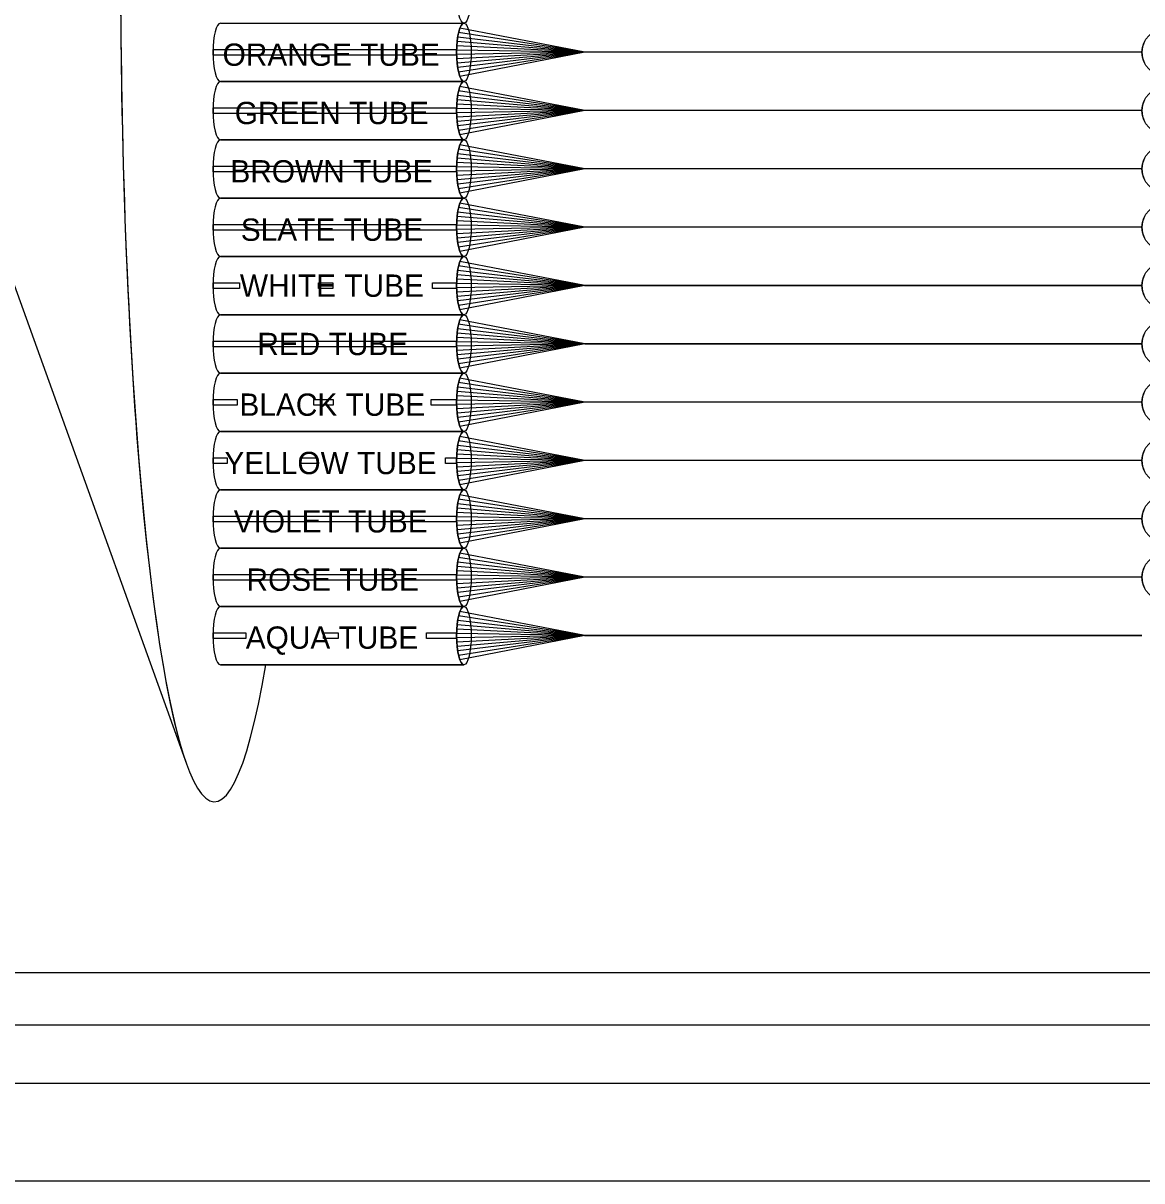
# Model space of a CAD drawing. Extents: x 1805893 to 1833564, y 708898 to 716199.
# Drawn here: x 1831608.1 to 1831723.1, y 714257.9 to 714377 of the extents above; entities that cross this region are included whole.
import ezdxf

# ---------------------------------------------------------------- set-up
doc = ezdxf.new("R2010")
doc.units = 0
for name, color, linetype in [('BR_P_Sub_Hidden', 7, 'Continuous'), ('SH_Border', 7, 'Continuous'), ('SH_Cut_Line', 7, 'Continuous'), ('SH_Data', 7, 'Continuous')]:
    doc.layers.add(name, color=color, linetype=linetype)

msp = doc.modelspace()

# ---------------------------------------------------------------- linework, layer by layer
at = {"layer": 'BR_P_Sub_Hidden'}
for points in [[(1831500.32, 714509.57), (1831957.51, 714509.57), (1831957.51, 714273.91), (1831500.32, 714273.91)], [(1831570.12, 714505.91), (1831894.14, 714505.91), (1831894.14, 714279.3), (1831570.12, 714279.3)]]:
    msp.add_lwpolyline(points, close=True, dxfattribs=at)
at = {"layer": 'SH_Border'}
msp.add_lwpolyline([(1831362.49, 714687.91), (1831992.49, 714687.91), (1831992.49, 714267.91), (1831362.49, 714267.91)], close=True, dxfattribs=at)
at = {"layer": 'SH_Cut_Line'}
msp.add_lwpolyline([(1831322.49, 714257.91), (1832002.49, 714257.91), (1832002.49, 714697.91), (1831322.49, 714697.91)], close=True, dxfattribs=at)
at = {"layer": 'SH_Data'}
for p, q in [((1831628.36, 714376.99), (1831653.41, 714376.99)), ((1831665.83, 714373.99), (1831652.85, 714376.01)), ((1831665.83, 714373.99), (1831652.98, 714376.46)), ((1831665.83, 714373.99), (1831652.71, 714375.11)), ((1831665.83, 714373.99), (1831652.77, 714375.56)), ((1831665.83, 714373.99), (1831652.66, 714374.21)), ((1831665.83, 714373.99), (1831652.66, 714373.76)), ((1831665.83, 714373.99), (1831652.67, 714374.66)), ((1831665.83, 714373.99), (1831652.67, 714373.31)), ((1831665.83, 714373.99), (1831652.71, 714372.86)), ((1831665.83, 714373.99), (1831652.77, 714372.41)), ((1831665.83, 714373.99), (1831652.85, 714371.96)), ((1831665.83, 714373.99), (1831652.98, 714371.51)), ((1831723.13, 714373.99), (1831665.83, 714373.99)), ((1831723.13, 714373.99), (1831665.83, 714373.99)), ((1831628.36, 714370.99), (1831653.41, 714370.99)), ((1831653.41, 714370.99), (1831628.36, 714370.99)), ((1831665.83, 714367.99), (1831652.98, 714370.46)), ((1831665.83, 714367.99), (1831652.71, 714369.11)), ((1831665.83, 714367.99), (1831652.77, 714369.56)), ((1831665.83, 714367.99), (1831652.85, 714370.01)), ((1831665.83, 714367.99), (1831652.66, 714368.21)), ((1831665.83, 714367.99), (1831652.66, 714367.76)), ((1831665.83, 714367.99), (1831652.67, 714368.66)), ((1831665.83, 714367.99), (1831652.67, 714367.31)), ((1831665.83, 714367.99), (1831652.71, 714366.86)), ((1831665.83, 714367.99), (1831652.77, 714366.41)), ((1831665.83, 714367.99), (1831652.85, 714365.96)), ((1831665.83, 714367.99), (1831652.98, 714365.51)), ((1831723.13, 714367.99), (1831665.83, 714367.99)), ((1831723.13, 714367.99), (1831665.83, 714367.99)), ((1831653.41, 714364.99), (1831628.36, 714364.99)), ((1831628.36, 714364.99), (1831653.41, 714364.99)), ((1831665.83, 714361.99), (1831652.98, 714364.46)), ((1831665.83, 714361.99), (1831652.71, 714363.11)), ((1831665.83, 714361.99), (1831652.77, 714363.56)), ((1831665.83, 714361.99), (1831652.85, 714364.01)), ((1831665.83, 714361.99), (1831652.66, 714362.21)), ((1831665.83, 714361.99), (1831652.66, 714361.76)), ((1831665.83, 714361.99), (1831652.67, 714362.66)), ((1831665.83, 714361.99), (1831652.67, 714361.31)), ((1831665.83, 714361.99), (1831652.71, 714360.86)), ((1831665.83, 714361.99), (1831652.77, 714360.41)), ((1831665.83, 714361.99), (1831652.85, 714359.96)), ((1831665.83, 714361.99), (1831652.98, 714359.51)), ((1831723.13, 714361.99), (1831665.83, 714361.99)), ((1831723.13, 714361.99), (1831665.83, 714361.99)), ((1831653.41, 714358.99), (1831628.36, 714358.99)), ((1831628.36, 714358.99), (1831653.41, 714358.99)), ((1831665.83, 714355.99), (1831652.98, 714358.46)), ((1831665.83, 714355.99), (1831652.71, 714357.11)), ((1831665.83, 714355.99), (1831652.77, 714357.56)), ((1831665.83, 714355.99), (1831652.85, 714358.01)), ((1831665.83, 714355.99), (1831652.66, 714356.21)), ((1831665.83, 714355.99), (1831652.66, 714355.76)), ((1831665.83, 714355.99), (1831652.67, 714356.66)), ((1831665.83, 714355.99), (1831652.67, 714355.31)), ((1831665.83, 714355.99), (1831652.71, 714354.86)), ((1831665.83, 714355.99), (1831652.77, 714354.41)), ((1831665.83, 714355.99), (1831652.85, 714353.96)), ((1831665.83, 714355.99), (1831652.98, 714353.51)), ((1831723.13, 714355.99), (1831665.83, 714355.99)), ((1831723.13, 714355.99), (1831665.83, 714355.99)), ((1831653.41, 714352.99), (1831628.36, 714352.99)), ((1831628.36, 714352.99), (1831653.41, 714352.99)), ((1831665.83, 714349.99), (1831652.98, 714352.46)), ((1831665.83, 714349.99), (1831652.71, 714351.11)), ((1831665.83, 714349.99), (1831652.77, 714351.56)), ((1831665.83, 714349.99), (1831652.85, 714352.01)), ((1831665.83, 714349.99), (1831652.66, 714350.21)), ((1831665.83, 714349.99), (1831652.66, 714349.76)), ((1831665.83, 714349.99), (1831652.67, 714350.66)), ((1831665.83, 714349.99), (1831652.67, 714349.31)), ((1831665.83, 714349.99), (1831652.71, 714348.86)), ((1831665.83, 714349.99), (1831652.77, 714348.41)), ((1831665.83, 714349.99), (1831652.85, 714347.96)), ((1831665.83, 714349.99), (1831652.98, 714347.51)), ((1831723.13, 714349.99), (1831665.83, 714349.99)), ((1831723.13, 714349.96), (1831665.83, 714349.94)), ((1831653.41, 714346.99), (1831628.36, 714346.99)), ((1831628.36, 714346.99), (1831653.41, 714346.99)), ((1831665.83, 714343.99), (1831652.98, 714346.46)), ((1831665.83, 714343.99), (1831652.71, 714345.11)), ((1831665.83, 714343.99), (1831652.77, 714345.56)), ((1831665.83, 714343.99), (1831652.85, 714346.01)), ((1831665.83, 714343.99), (1831652.66, 714344.21)), ((1831665.83, 714343.99), (1831652.66, 714343.76)), ((1831665.83, 714343.99), (1831652.67, 714344.66)), ((1831665.83, 714343.99), (1831652.67, 714343.31)), ((1831665.83, 714343.99), (1831652.71, 714342.86)), ((1831665.83, 714343.99), (1831652.77, 714342.41)), ((1831665.83, 714343.99), (1831652.85, 714341.96)), ((1831665.83, 714343.99), (1831652.98, 714341.51)), ((1831665.83, 714343.99), (1831723.13, 714343.99)), ((1831723.13, 714343.99), (1831665.83, 714343.99)), ((1831653.41, 714340.99), (1831628.36, 714340.99)), ((1831628.36, 714340.99), (1831653.41, 714340.99)), ((1831665.83, 714337.99), (1831652.98, 714340.46)), ((1831665.83, 714337.99), (1831652.71, 714339.11)), ((1831665.83, 714337.99), (1831652.77, 714339.56)), ((1831665.83, 714337.99), (1831652.85, 714340.01)), ((1831665.83, 714337.99), (1831652.66, 714338.21)), ((1831665.83, 714337.99), (1831652.66, 714337.76)), ((1831665.83, 714337.99), (1831652.67, 714338.66)), ((1831665.83, 714337.99), (1831652.67, 714337.31)), ((1831665.83, 714337.99), (1831652.71, 714336.86)), ((1831665.83, 714337.99), (1831652.77, 714336.41)), ((1831665.83, 714337.99), (1831652.85, 714335.96)), ((1831665.83, 714337.99), (1831652.98, 714335.51)), ((1831723.13, 714337.99), (1831665.83, 714337.99)), ((1831723.13, 714337.99), (1831665.83, 714337.99)), ((1831628.36, 714334.99), (1831653.41, 714334.99)), ((1831653.41, 714334.99), (1831628.36, 714334.99)), ((1831665.83, 714331.99), (1831652.98, 714334.46)), ((1831665.83, 714331.99), (1831652.77, 714333.56)), ((1831665.83, 714331.99), (1831652.85, 714334.01)), ((1831665.83, 714331.99), (1831652.66, 714332.21)), ((1831665.83, 714331.99), (1831652.66, 714331.76)), ((1831665.83, 714331.99), (1831652.67, 714332.66)), ((1831665.83, 714331.99), (1831652.67, 714331.31)), ((1831665.83, 714331.99), (1831652.71, 714333.11)), ((1831665.83, 714331.99), (1831652.71, 714330.86)), ((1831665.83, 714331.99), (1831652.77, 714330.41)), ((1831665.83, 714331.99), (1831652.85, 714329.96)), ((1831665.83, 714331.99), (1831652.98, 714329.51)), ((1831723.13, 714331.99), (1831665.83, 714331.99)), ((1831723.13, 714331.99), (1831665.83, 714331.99)), ((1831653.41, 714328.99), (1831628.36, 714328.99)), ((1831628.36, 714328.99), (1831653.41, 714328.99)), ((1831665.83, 714325.99), (1831652.98, 714328.46)), ((1831665.83, 714325.99), (1831652.77, 714327.56)), ((1831665.83, 714325.99), (1831652.85, 714328.01)), ((1831665.83, 714325.99), (1831652.66, 714326.21)), ((1831665.83, 714325.99), (1831652.67, 714326.66)), ((1831665.83, 714325.99), (1831652.71, 714327.11)), ((1831665.83, 714325.99), (1831652.66, 714325.76)), ((1831665.83, 714325.99), (1831652.67, 714325.31)), ((1831665.83, 714325.99), (1831652.71, 714324.86)), ((1831665.83, 714325.99), (1831652.77, 714324.41)), ((1831665.83, 714325.99), (1831652.85, 714323.96)), ((1831665.83, 714325.99), (1831652.98, 714323.51)), ((1831723.13, 714325.99), (1831665.83, 714325.99)), ((1831723.13, 714325.99), (1831665.83, 714325.99)), ((1831653.41, 714322.99), (1831628.36, 714322.99)), ((1831628.36, 714322.99), (1831653.41, 714322.99)), ((1831665.83, 714319.99), (1831652.98, 714322.46)), ((1831665.83, 714319.99), (1831652.77, 714321.56)), ((1831665.83, 714319.99), (1831652.85, 714322.01)), ((1831665.83, 714319.99), (1831652.66, 714320.21)), ((1831665.83, 714319.99), (1831652.67, 714320.66)), ((1831665.83, 714319.99), (1831652.71, 714321.11)), ((1831665.83, 714319.99), (1831652.66, 714319.76)), ((1831665.83, 714319.99), (1831652.67, 714319.31)), ((1831665.83, 714319.99), (1831652.71, 714318.86)), ((1831665.83, 714319.99), (1831652.77, 714318.41)), ((1831665.83, 714319.99), (1831652.85, 714317.96)), ((1831665.83, 714319.99), (1831652.98, 714317.51)), ((1831723.13, 714319.99), (1831665.83, 714319.99)), ((1831723.13, 714319.99), (1831665.83, 714319.99)), ((1831653.41, 714316.99), (1831628.36, 714316.99)), ((1831628.36, 714316.99), (1831653.41, 714316.99)), ((1831665.83, 714313.99), (1831652.77, 714315.56)), ((1831665.83, 714313.99), (1831652.85, 714316.01)), ((1831665.83, 714313.99), (1831652.98, 714316.46)), ((1831665.83, 714313.99), (1831652.66, 714314.21)), ((1831665.83, 714313.99), (1831652.67, 714314.66)), ((1831665.83, 714313.99), (1831652.71, 714315.11)), ((1831665.83, 714313.99), (1831652.66, 714313.76)), ((1831665.83, 714313.99), (1831652.67, 714313.31)), ((1831665.83, 714313.99), (1831652.71, 714312.86)), ((1831665.83, 714313.99), (1831652.77, 714312.41)), ((1831665.83, 714313.99), (1831652.85, 714311.96)), ((1831665.83, 714313.99), (1831652.98, 714311.51)), ((1831723.13, 714313.99), (1831665.83, 714313.99)), ((1831723.13, 714313.96), (1831665.83, 714313.94)), ((1831653.41, 714310.99), (1831628.36, 714310.99)), ((1831628.36, 714310.99), (1831653.41, 714310.99)), ((1831653.41, 714310.99), (1831633.05, 714310.99))]:
    msp.add_line(p, q, dxfattribs=at)
msp.add_lwpolyline([(1831624.88, 714465.18), (1831595.29, 714382.99), (1831624.88, 714300.79)], dxfattribs=at)
msp.add_lwpolyline([(1831624.88, 714465.18), (1831595.29, 714382.99), (1831624.88, 714300.79)], dxfattribs=at)
for points in [[(1831627.61, 714374.29), (1831652.66, 714374.29), (1831652.66, 714373.69), (1831627.61, 714373.69)], [(1831627.61, 714368.29), (1831652.66, 714368.29), (1831652.66, 714367.69), (1831627.61, 714367.69)], [(1831627.61, 714362.29), (1831652.66, 714362.29), (1831652.66, 714361.69), (1831627.61, 714361.69)], [(1831627.61, 714356.29), (1831652.66, 714356.29), (1831652.66, 714355.69), (1831627.61, 714355.69)], [(1831627.61, 714350.29), (1831630.34, 714350.29), (1831630.34, 714349.69), (1831627.61, 714349.69)], [(1831638.44, 714350.29), (1831639.92, 714350.29), (1831639.92, 714349.69), (1831638.44, 714349.69)], [(1831650.17, 714350.29), (1831652.66, 714350.29), (1831652.66, 714349.69), (1831650.17, 714349.69)], [(1831627.61, 714344.29), (1831652.66, 714344.29), (1831652.66, 714343.69), (1831627.61, 714343.69)], [(1831627.61, 714338.29), (1831630.09, 714338.29), (1831630.09, 714337.69), (1831627.61, 714337.69)], [(1831637.99, 714338.29), (1831639.96, 714338.29), (1831639.96, 714337.69), (1831637.99, 714337.69)], [(1831650.05, 714338.29), (1831652.66, 714338.29), (1831652.66, 714337.69), (1831650.05, 714337.69)], [(1831627.61, 714332.29), (1831629.07, 714332.29), (1831629.07, 714331.69), (1831627.61, 714331.69)], [(1831636.57, 714332.29), (1831638.29, 714332.29), (1831638.29, 714331.69), (1831636.57, 714331.69)], [(1831651.53, 714332.29), (1831652.66, 714332.29), (1831652.66, 714331.69), (1831651.53, 714331.69)], [(1831627.61, 714326.29), (1831652.66, 714326.29), (1831652.66, 714325.69), (1831627.61, 714325.69)], [(1831627.61, 714320.29), (1831652.66, 714320.29), (1831652.66, 714319.69), (1831627.61, 714319.69)], [(1831627.61, 714314.29), (1831630.98, 714314.29), (1831630.98, 714313.69), (1831627.61, 714313.69)], [(1831638.97, 714314.29), (1831640.49, 714314.29), (1831640.49, 714313.69), (1831638.97, 714313.69)], [(1831649.56, 714314.29), (1831652.66, 714314.29), (1831652.66, 714313.69), (1831649.56, 714313.69)]]:
    msp.add_lwpolyline(points, close=True, dxfattribs=at)
for centre in [(1831725.55, 714373.99), (1831725.55, 714367.99), (1831725.55, 714361.99), (1831725.55, 714355.99), (1831725.55, 714349.99), (1831725.55, 714343.99), (1831725.55, 714337.99), (1831725.55, 714331.99), (1831725.55, 714325.99), (1831725.55, 714319.99)]:
    msp.add_circle(centre, 2.41, dxfattribs=at)
for centre in [(1831725.55, 714373.99), (1831725.55, 714367.99), (1831725.55, 714361.99), (1831725.55, 714355.99), (1831725.55, 714349.99), (1831725.55, 714343.99), (1831725.55, 714337.99), (1831725.55, 714331.99), (1831725.55, 714325.99), (1831725.55, 714319.99)]:
    msp.add_arc(centre, 2.41, 152.353, 207.647, dxfattribs=at)
for centre, major_axis, ratio, start_param, end_param in [((1831627.75, 714382.99), (0, -86.09), 0.112175, 2.561295, 6.863483), ((1831627.75, 714382.99), (0, -86.09), 0.112175, 2.561295, 6.863483), ((1831627.75, 714382.99), (0, -86.09), 0.112175, 3.443628, 5.98115), ((1831628.36, 714373.99), (0, -3), 0.25, 3.141593, 6.283185), ((1831628.36, 714373.99), (0, -3), 0.25, 3.141593, 6.283185), ((1831653.41, 714373.99), (0, -3), 0.25, 3.141593, 6.283185), ((1831628.36, 714367.99), (0, -3), 0.25, 3.141593, 6.283185), ((1831628.36, 714367.99), (0, -3), 0.25, 3.141593, 6.283185), ((1831653.41, 714367.99), (0, -3), 0.25, 3.141593, 6.283185), ((1831628.36, 714361.99), (0, -3), 0.25, 3.141593, 6.283185), ((1831628.36, 714361.99), (0, -3), 0.25, 3.141593, 6.283185), ((1831653.41, 714361.99), (0, -3), 0.25, 3.141593, 6.283185), ((1831628.36, 714355.99), (0, -3), 0.25, 3.141593, 6.283185), ((1831628.36, 714355.99), (0, -3), 0.25, 3.141593, 6.283185), ((1831653.41, 714355.99), (0, -3), 0.25, 3.141593, 6.283185), ((1831628.36, 714349.99), (0, -3), 0.25, 3.141593, 6.283185), ((1831628.36, 714349.99), (0, -3), 0.25, 3.141593, 6.283185), ((1831653.41, 714349.99), (0, -3), 0.25, 3.141593, 6.283185), ((1831628.36, 714343.99), (0, -3), 0.25, 3.141593, 6.283185), ((1831628.36, 714343.99), (0, -3), 0.25, 3.141593, 6.283185), ((1831653.41, 714343.99), (0, -3), 0.25, 3.141593, 6.283185), ((1831628.36, 714337.99), (0, -3), 0.25, 3.141593, 6.283185), ((1831628.36, 714337.99), (0, -3), 0.25, 3.141593, 6.283185), ((1831653.41, 714337.99), (0, -3), 0.25, 3.141593, 6.283185), ((1831628.36, 714331.99), (0, -3), 0.25, 3.141593, 6.283185), ((1831628.36, 714331.99), (0, -3), 0.25, 3.141593, 6.283185), ((1831653.41, 714331.99), (0, -3), 0.25, 3.141593, 6.283185), ((1831628.36, 714325.99), (0, -3), 0.25, 3.141593, 6.283185), ((1831628.36, 714325.99), (0, -3), 0.25, 3.141593, 6.283185), ((1831653.41, 714325.99), (0, -3), 0.25, 3.141593, 6.283185), ((1831628.36, 714319.99), (0, -3), 0.25, 3.141593, 6.283185), ((1831628.36, 714319.99), (0, -3), 0.25, 3.141593, 6.283185), ((1831653.41, 714319.99), (0, -3), 0.25, 3.141593, 6.283185), ((1831628.36, 714313.99), (0, -3), 0.25, 3.141593, 6.283185), ((1831628.36, 714313.99), (0, -3), 0.25, 3.141593, 6.283185), ((1831653.41, 714313.99), (0, -3), 0.25, 3.141593, 6.283185)]:
    msp.add_ellipse(centre, major_axis=major_axis, ratio=ratio, start_param=start_param, end_param=end_param, dxfattribs=at)
for centre in [(1831653.41, 714379.99), (1831653.41, 714373.99), (1831653.41, 714367.99), (1831653.41, 714361.99), (1831653.41, 714355.99), (1831653.41, 714349.99), (1831653.41, 714343.99), (1831653.41, 714337.99), (1831653.41, 714331.99), (1831653.41, 714325.99), (1831653.41, 714319.99), (1831653.41, 714313.99)]:
    msp.add_ellipse(centre, major_axis=(0, -3), ratio=0.25, dxfattribs=at)

# ---------------------------------------------------------------- texts
for s, height, p in [('ORANGE TUBE', 2.2947, (1831628.59, 714372.6)), ('GREEN TUBE', 2.295, (1831629.84, 714366.6)), ('BROWN TUBE', 2.295, (1831629.39, 714360.6)), ('SLATE TUBE', 2.295, (1831630.46, 714354.6)), ('WHITE TUBE', 2.295, (1831630.37, 714348.84)), ('RED TUBE', 2.295, (1831632.16, 714342.84)), ('BLACK TUBE', 2.295, (1831630.32, 714336.6)), ('YELLOW TUBE', 2.2947, (1831628.78, 714330.6)), ('VIOLET TUBE', 2.2947, (1831629.73, 714324.6)), ('ROSE TUBE', 2.295, (1831631.05, 714318.6)), ('AQUA TUBE', 2.295, (1831630.97, 714312.64))]:
    msp.add_text(s, height=height, dxfattribs=at).set_placement(p)

doc.saveas('drawing.dxf')
